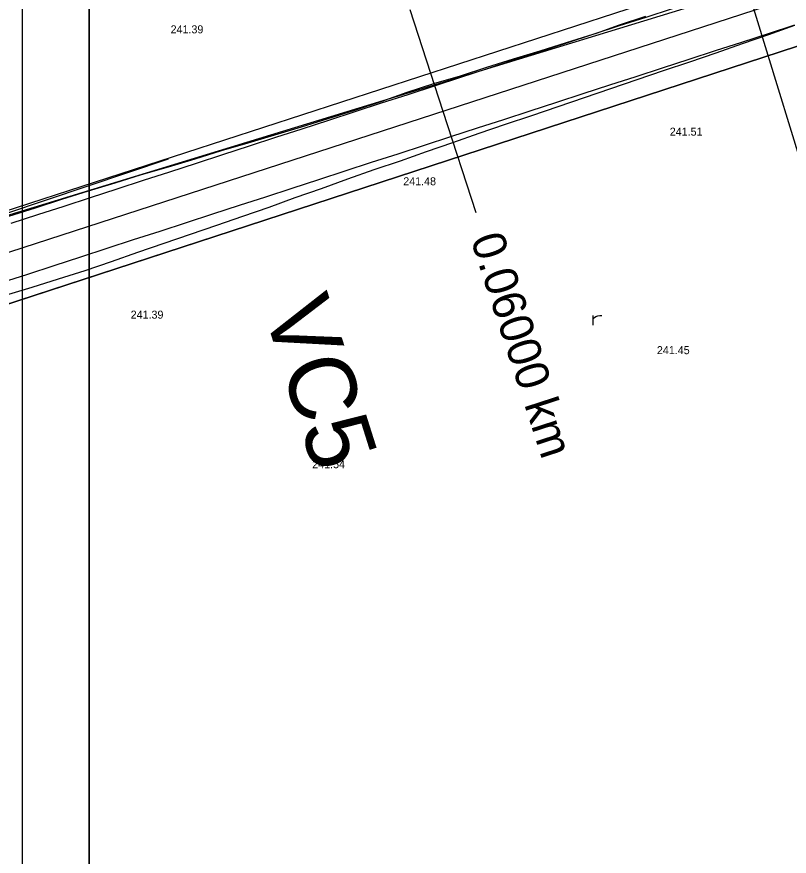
# Model space of a CAD drawing. Extents: x -555887 to -552101, y -1100251 to -1096546.
# Drawn here: x -554645 to -554587.2, y -1098469.6 to -1098406.7 of the extents above; entities that cross this region are included whole.
import ezdxf

# ---------------------------------------------------------------- set-up
doc = ezdxf.new("R2010")
doc.units = 0
for name, color, linetype in [('PARCELY_cesty', 7, 'Continuous'), ('POLYGONY_SITUACE_PF', 7, 'Continuous'), ('POLYGONY_SITUACE_PF_POPISY', 7, 'Continuous'), ('POLYGONY_SITUACE_PO', 7, 'Continuous'), ('ram_VC4', 7, 'Continuous'), ('ROZHLED_parcela_cesty', 7, 'Continuous'), ('ROZHLED_ram_legenda_1', 7, 'Continuous'), ('Výškopis', 7, 'Continuous'), ('ZSST', 7, 'Continuous'), ('zájem', 7, 'Continuous')]:
    doc.layers.add(name, color=color, linetype=linetype)

msp = doc.modelspace()

# ---------------------------------------------------------------- linework, layer by layer
at = {"layer": 'PARCELY_cesty'}
msp.add_lwpolyline([(-554666.58, -1098424.3), (-554661.613, -1098426.35), (-554474.619, -1098365.555), (-554470.001, -1098364.247), (-554462.918, -1098362.998), (-554455.97, -1098362.75), (-554451.048, -1098362.623), (-554296.95, -1098373.16), (-554290.885, -1098371.599), (-554270.388, -1098373.304), (-554264.04, -1098376.17), (-554253.344, -1098377.565), (-554081.032, -1098403.398), (-554065.658, -1098405.306), (-554039.82, -1098406.01), (-554011.196, -1098408.42), (-553994.13, -1098410.89)], dxfattribs=at)
at = {"layer": 'POLYGONY_SITUACE_PF'}
for p, q in [((-554615.609, -1098406.135), (-554613.135, -1098413.743)), ((-554613.135, -1098413.743), (-554610.662, -1098421.351))]:
    msp.add_line(p, q, dxfattribs=at)
at = {"layer": 'POLYGONY_SITUACE_PO'}
for p, q in [((-554670.195, -1098432.295), (-554473.746, -1098368.426)), ((-554597.904, -1098406.688), (-554595.922, -1098406.044)), ((-554597.904, -1098406.688), (-554595.922, -1098406.044)), ((-554599.904, -1098407.275), (-554597.928, -1098406.612)), ((-554599.885, -1098407.332), (-554597.904, -1098406.688)), ((-554599.885, -1098407.332), (-554597.904, -1098406.688)), ((-554601.866, -1098407.977), (-554599.885, -1098407.332)), ((-554601.866, -1098407.977), (-554599.885, -1098407.332)), ((-554601.606, -1098407.892), (-554599.904, -1098407.275)), ((-554588.742, -1098407.916), (-554586.761, -1098407.272)), ((-554588.742, -1098407.916), (-554586.761, -1098407.272)), ((-554588.716, -1098407.995), (-554586.751, -1098407.3)), ((-554603.854, -1098408.601), (-554601.869, -1098407.968)), ((-554603.847, -1098408.621), (-554601.866, -1098407.977)), ((-554603.847, -1098408.621), (-554601.866, -1098407.977)), ((-554601.869, -1098407.968), (-554601.606, -1098407.892)), ((-554590.723, -1098408.56), (-554588.742, -1098407.916)), ((-554590.723, -1098408.56), (-554588.742, -1098407.916)), ((-554605.844, -1098409.219), (-554603.854, -1098408.601)), ((-554592.704, -1098409.204), (-554590.723, -1098408.56)), ((-554592.704, -1098409.204), (-554590.723, -1098408.56)), ((-554590.683, -1098408.684), (-554588.716, -1098407.995)), ((-554607.839, -1098409.821), (-554605.844, -1098409.219)), ((-554605.829, -1098409.265), (-554603.847, -1098408.621)), ((-554605.829, -1098409.265), (-554603.847, -1098408.621)), ((-554594.686, -1098409.848), (-554592.704, -1098409.204)), ((-554594.686, -1098409.848), (-554592.704, -1098409.204)), ((-554592.65, -1098409.37), (-554590.683, -1098408.684)), ((-554609.83, -1098410.434), (-554607.839, -1098409.821)), ((-554607.81, -1098409.909), (-554605.829, -1098409.265)), ((-554607.81, -1098409.909), (-554605.829, -1098409.265)), ((-554596.667, -1098410.492), (-554594.686, -1098409.848)), ((-554596.667, -1098410.492), (-554594.686, -1098409.848)), ((-554594.625, -1098410.036), (-554592.65, -1098409.37)), ((-554611.801, -1098411.108), (-554609.83, -1098410.434)), ((-554609.791, -1098410.553), (-554607.81, -1098409.909)), ((-554609.791, -1098410.553), (-554607.81, -1098409.909)), ((-554598.648, -1098411.136), (-554596.667, -1098410.492)), ((-554598.648, -1098411.136), (-554596.667, -1098410.492)), ((-554596.599, -1098410.701), (-554594.625, -1098410.036)), ((-554613.805, -1098411.682), (-554611.801, -1098411.108)), ((-554611.772, -1098411.197), (-554609.791, -1098410.553)), ((-554611.772, -1098411.197), (-554609.791, -1098410.553)), ((-554598.569, -1098411.381), (-554596.599, -1098410.701)), ((-554615.789, -1098412.32), (-554613.805, -1098411.682)), ((-554613.754, -1098411.841), (-554611.772, -1098411.197)), ((-554613.754, -1098411.841), (-554611.772, -1098411.197)), ((-554600.629, -1098411.781), (-554598.648, -1098411.136)), ((-554600.629, -1098411.781), (-554598.648, -1098411.136)), ((-554600.542, -1098412.049), (-554598.569, -1098411.381)), ((-554617.751, -1098413.023), (-554615.789, -1098412.32)), ((-554615.735, -1098412.486), (-554613.754, -1098411.841)), ((-554615.735, -1098412.486), (-554613.754, -1098411.841)), ((-554602.611, -1098412.425), (-554600.629, -1098411.781)), ((-554602.611, -1098412.425), (-554600.629, -1098411.781)), ((-554602.513, -1098412.726), (-554600.542, -1098412.049)), ((-554617.716, -1098413.13), (-554615.735, -1098412.486)), ((-554617.716, -1098413.13), (-554615.735, -1098412.486)), ((-554604.592, -1098413.069), (-554602.611, -1098412.425)), ((-554604.592, -1098413.069), (-554602.611, -1098412.425)), ((-554604.488, -1098413.389), (-554602.513, -1098412.726)), ((-554619.731, -1098413.67), (-554617.751, -1098413.023)), ((-554619.697, -1098413.774), (-554617.716, -1098413.13)), ((-554619.697, -1098413.774), (-554617.716, -1098413.13)), ((-554606.573, -1098413.713), (-554604.592, -1098413.069)), ((-554606.573, -1098413.713), (-554604.592, -1098413.069)), ((-554606.461, -1098414.059), (-554604.488, -1098413.389)), ((-554621.721, -1098414.288), (-554619.731, -1098413.67)), ((-554621.679, -1098414.418), (-554619.697, -1098413.774)), ((-554621.679, -1098414.418), (-554619.697, -1098413.774)), ((-554608.554, -1098414.357), (-554606.573, -1098413.713)), ((-554608.554, -1098414.357), (-554606.573, -1098413.713)), ((-554608.433, -1098414.73), (-554606.461, -1098414.059)), ((-554623.71, -1098414.909), (-554621.721, -1098414.288)), ((-554623.66, -1098415.062), (-554621.679, -1098414.418)), ((-554623.66, -1098415.062), (-554621.679, -1098414.418)), ((-554610.536, -1098415.001), (-554608.554, -1098414.357)), ((-554610.536, -1098415.001), (-554608.554, -1098414.357)), ((-554610.407, -1098415.398), (-554608.433, -1098414.73)), ((-554627.701, -1098416.108), (-554625.702, -1098415.52)), ((-554625.702, -1098415.52), (-554623.71, -1098414.909)), ((-554625.641, -1098415.706), (-554623.66, -1098415.062)), ((-554625.641, -1098415.706), (-554623.66, -1098415.062)), ((-554612.517, -1098415.645), (-554610.536, -1098415.001)), ((-554612.517, -1098415.645), (-554610.536, -1098415.001)), ((-554612.371, -1098416.096), (-554610.407, -1098415.398)), ((-554629.705, -1098416.684), (-554627.701, -1098416.108)), ((-554627.622, -1098416.35), (-554625.641, -1098415.706)), ((-554627.622, -1098416.35), (-554625.641, -1098415.706)), ((-554614.498, -1098416.29), (-554612.517, -1098415.645)), ((-554614.498, -1098416.29), (-554612.517, -1098415.645)), ((-554614.34, -1098416.777), (-554612.371, -1098416.096)), ((-554631.689, -1098417.32), (-554629.705, -1098416.684)), ((-554629.604, -1098416.995), (-554627.622, -1098416.35)), ((-554629.604, -1098416.995), (-554627.622, -1098416.35)), ((-554616.479, -1098416.934), (-554614.498, -1098416.29)), ((-554616.479, -1098416.934), (-554614.498, -1098416.29)), ((-554616.308, -1098417.46), (-554614.34, -1098416.777)), ((-554633.684, -1098417.921), (-554631.689, -1098417.32)), ((-554631.585, -1098417.639), (-554629.604, -1098416.995)), ((-554631.585, -1098417.639), (-554629.604, -1098416.995)), ((-554618.461, -1098417.578), (-554616.479, -1098416.934)), ((-554618.461, -1098417.578), (-554616.479, -1098416.934)), ((-554635.689, -1098418.493), (-554633.684, -1098417.921)), ((-554633.566, -1098418.283), (-554631.585, -1098417.639)), ((-554633.566, -1098418.283), (-554631.585, -1098417.639)), ((-554620.442, -1098418.222), (-554618.461, -1098417.578)), ((-554620.442, -1098418.222), (-554618.461, -1098417.578)), ((-554618.282, -1098418.128), (-554616.308, -1098417.46)), ((-554637.677, -1098419.116), (-554635.689, -1098418.493)), ((-554635.547, -1098418.927), (-554633.566, -1098418.283)), ((-554635.547, -1098418.927), (-554633.566, -1098418.283)), ((-554622.423, -1098418.866), (-554620.442, -1098418.222)), ((-554622.423, -1098418.866), (-554620.442, -1098418.222)), ((-554620.245, -1098418.828), (-554618.282, -1098418.128)), ((-554639.671, -1098419.72), (-554637.677, -1098419.116)), ((-554637.529, -1098419.571), (-554635.547, -1098418.927)), ((-554637.529, -1098419.571), (-554635.547, -1098418.927)), ((-554624.404, -1098419.51), (-554622.423, -1098418.866)), ((-554624.404, -1098419.51), (-554622.423, -1098418.866)), ((-554622.206, -1098419.535), (-554620.245, -1098418.828)), ((-554641.658, -1098420.345), (-554639.671, -1098419.72)), ((-554639.51, -1098420.215), (-554637.529, -1098419.571)), ((-554639.51, -1098420.215), (-554637.529, -1098419.571)), ((-554626.386, -1098420.154), (-554624.404, -1098419.51)), ((-554626.386, -1098420.154), (-554624.404, -1098419.51)), ((-554624.178, -1098420.208), (-554622.206, -1098419.535)), ((-554643.641, -1098420.985), (-554641.658, -1098420.345)), ((-554641.491, -1098420.859), (-554639.51, -1098420.215)), ((-554641.491, -1098420.859), (-554639.51, -1098420.215)), ((-554628.367, -1098420.799), (-554626.386, -1098420.154)), ((-554628.367, -1098420.799), (-554626.386, -1098420.154)), ((-554626.134, -1098420.929), (-554624.178, -1098420.208)), ((-554645.628, -1098421.611), (-554643.641, -1098420.985)), ((-554643.473, -1098421.503), (-554641.491, -1098420.859)), ((-554643.473, -1098421.503), (-554641.491, -1098420.859)), ((-554630.348, -1098421.443), (-554628.367, -1098420.799)), ((-554630.348, -1098421.443), (-554628.367, -1098420.799)), ((-554628.098, -1098421.627), (-554626.134, -1098420.929)), ((-554645.454, -1098422.148), (-554643.473, -1098421.503)), ((-554645.454, -1098422.148), (-554643.473, -1098421.503)), ((-554632.33, -1098422.087), (-554630.348, -1098421.443)), ((-554632.33, -1098422.087), (-554630.348, -1098421.443)), ((-554630.069, -1098422.301), (-554628.098, -1098421.627)), ((-554634.311, -1098422.731), (-554632.33, -1098422.087)), ((-554634.311, -1098422.731), (-554632.33, -1098422.087)), ((-554632.042, -1098422.971), (-554630.069, -1098422.301)), ((-554636.292, -1098423.375), (-554634.311, -1098422.731)), ((-554636.292, -1098423.375), (-554634.311, -1098422.731)), ((-554634.013, -1098423.647), (-554632.042, -1098422.971)), ((-554638.273, -1098424.019), (-554636.292, -1098423.375)), ((-554638.273, -1098424.019), (-554636.292, -1098423.375)), ((-554635.986, -1098424.316), (-554634.013, -1098423.647)), ((-554640.255, -1098424.663), (-554638.273, -1098424.019)), ((-554640.255, -1098424.663), (-554638.273, -1098424.019)), ((-554637.951, -1098425.01), (-554635.986, -1098424.316)), ((-554642.236, -1098425.307), (-554640.255, -1098424.663)), ((-554642.236, -1098425.307), (-554640.255, -1098424.663)), ((-554644.217, -1098425.952), (-554642.236, -1098425.307)), ((-554644.217, -1098425.952), (-554642.236, -1098425.307)), ((-554639.918, -1098425.697), (-554637.951, -1098425.01)), ((-554646.198, -1098426.596), (-554644.217, -1098425.952)), ((-554646.198, -1098426.596), (-554644.217, -1098425.952)), ((-554641.911, -1098426.306), (-554639.918, -1098425.697)), ((-554643.9, -1098426.926), (-554641.911, -1098426.306)), ((-554645.889, -1098427.546), (-554643.9, -1098426.926))]:
    msp.add_line(p, q, dxfattribs=at)
at = {"layer": 'ram_VC4'}
for points in [[(-554287.63, -1097875.47), (-554644.63, -1097875.47), (-554644.63, -1098505.47), (-554287.63, -1098505.47)], [(-554292.63, -1097880.47), (-554639.63, -1097880.47), (-554639.63, -1098500.47), (-554292.63, -1098500.47)]]:
    msp.add_lwpolyline(points, close=True, dxfattribs=at)
for points in [[(-554287.63, -1097875.47), (-554644.63, -1097875.47), (-554644.63, -1098505.47), (-554287.63, -1098505.47), (-554287.63, -1097875.47)], [(-554292.63, -1098500.47), (-554639.63, -1098500.47), (-554639.63, -1097880.47), (-554292.63, -1097880.47), (-554292.63, -1098500.47)]]:
    msp.add_lwpolyline(points, dxfattribs=at)
at = {"layer": 'ROZHLED_parcela_cesty'}
msp.add_lwpolyline([(-554633.71, -1098417.35), (-554661.23, -1098426.59), (-554663.91, -1098426.33), (-554666.3, -1098425.31), (-554663.51, -1098435.37), (-554662.161, -1098433.572), (-554623.985, -1098421.1)], dxfattribs=at)
at = {"layer": 'ROZHLED_ram_legenda_1'}
msp.add_lwpolyline([(-554736.692, -1098609.33), (-554820.873, -1098334.953), (-554629.67, -1098276.29), (-554545.488, -1098550.667), (-554736.692, -1098609.33)], dxfattribs=at)
msp.add_lwpolyline([(-554736.692, -1098609.33), (-554820.873, -1098334.953), (-554629.67, -1098276.29), (-554545.488, -1098550.667), (-554736.692, -1098609.33)], dxfattribs=at)
at = {"layer": 'ZSST'}
for points in [[(-554664.51, -1098427.29), (-554593.24, -1098405.5), (-554564.12, -1098396.39), (-554504.51, -1098380.38), (-554474.09, -1098371.8), (-554453.04, -1098367.02), (-554440.1, -1098364.81), (-554432.74, -1098364.37), (-554410.92, -1098364.7), (-554369.44, -1098366), (-554333.38, -1098368), (-554270.17, -1098373.82), (-554215.58, -1098380.33), (-554205.6, -1098382.24), (-554194.57, -1098383.81), (-554169.13, -1098388.36), (-554184.13, -1098381.1), (-554194.68, -1098382.34), (-554205.5, -1098381.25), (-554215.58, -1098380.33)], [(-554601.877, -1098429.796), (-554601.877, -1098429.064)], [(-554601.877, -1098429.3), (-554601.775, -1098429.205), (-554601.672, -1098429.142), (-554601.515, -1098429.095), (-554601.365, -1098429.072), (-554601.208, -1098429.064)]]:
    msp.add_lwpolyline(points, dxfattribs=at)
at = {"layer": 'zájem'}
for points in [[(-555057.79, -1098455.7), (-554947.91, -1098379.76), (-554868.79, -1098324.5), (-554807.83, -1098282.81), (-554734.83, -1098232.28), (-554733.03, -1098237.3), (-554723.03, -1098264.9), (-554699.69, -1098346.16), (-554674.86, -1098437.73), (-554672.03, -1098436.78), (-554666.38, -1098434.92), (-554663.87, -1098434.13), (-554584.1, -1098408.07), (-554542.63, -1098394.85), (-554461.77, -1098369.06), (-554380.5, -1098374.37), (-554285.56, -1098379.8), (-554280.9, -1098380.23), (-554271.92, -1098380.9), (-554131.79, -1098402.65)], [(-554131.79, -1098402.65), (-554271.92, -1098380.9), (-554280.9, -1098380.23), (-554285.56, -1098379.8), (-554380.5, -1098374.37), (-554461.77, -1098369.06), (-554542.63, -1098394.85), (-554584.1, -1098408.07), (-554663.87, -1098434.13), (-554666.38, -1098434.92), (-554672.03, -1098436.78), (-554674.86, -1098437.73), (-554699.69, -1098346.16), (-554723.03, -1098264.9), (-554733.03, -1098237.3), (-554734.83, -1098232.28), (-554807.83, -1098282.81), (-554868.79, -1098324.5), (-554947.91, -1098379.76), (-555057.79, -1098455.7)]]:
    msp.add_lwpolyline(points, dxfattribs=at)

# ---------------------------------------------------------------- texts
at = {"layer": 'POLYGONY_SITUACE_PF_POPISY'}
msp.add_text('0.06000 km', height=2.5, rotation=288.01012, dxfattribs=at).set_placement((-554611.071, -1098423.328))
at = {"layer": 'ROZHLED_ram_legenda_1'}
msp.add_text('VC5', height=5, rotation=287.48264, dxfattribs=at).set_placement((-554626.603, -1098428.592))
at = {"layer": 'Výškopis'}
for s, p in [('241.39', (-554633.522, -1098407.91)), ('241.51', (-554596.128, -1098415.58)), ('241.48', (-554616.092, -1098419.3)), ('241.39', (-554636.512, -1098429.3)), ('241.45', (-554597.09, -1098431.96)), ('241.54', (-554622.91, -1098440.51))]:
    msp.add_text(s, height=0.6, dxfattribs=at).set_placement(p)

doc.saveas('drawing.dxf')
